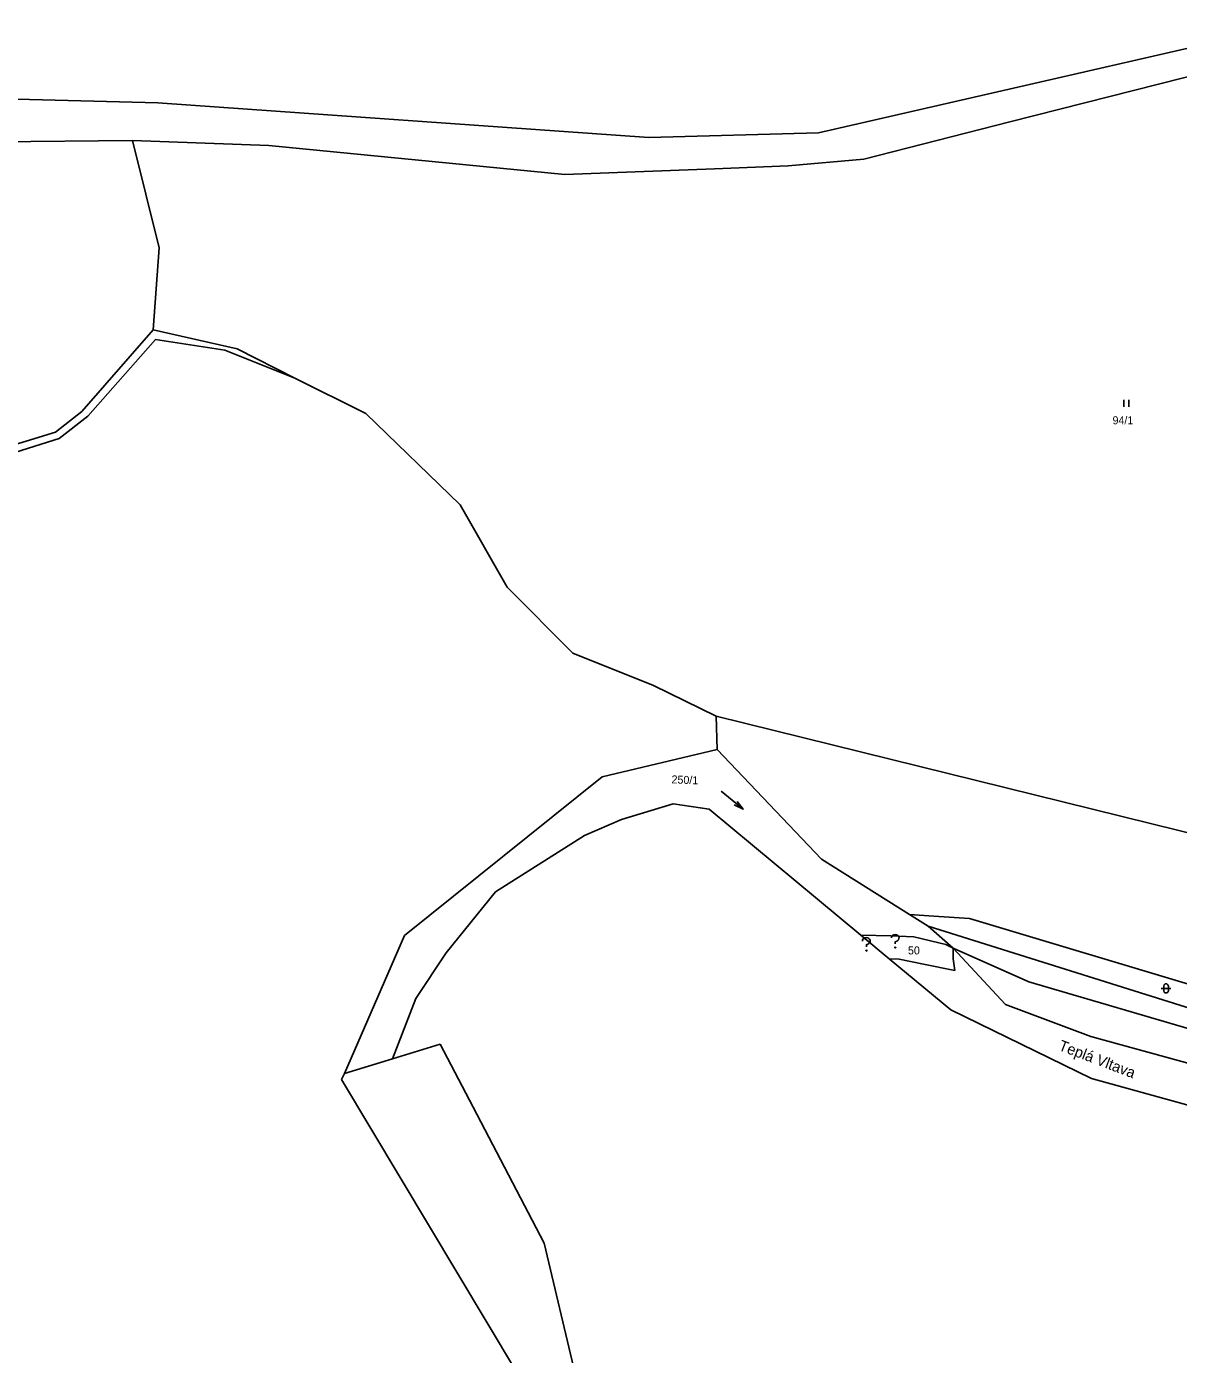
# Model space of a CAD drawing. Extents: x -811039 to -805820, y -1161436 to -1155864.
# Drawn here: x -809634.1 to -809389.3, y -1160727.4 to -1160445.2 of the extents above; entities that cross this region are included whole.
import ezdxf

# ---------------------------------------------------------------- set-up
doc = ezdxf.new("R2010")
doc.units = 0
for name, color, linetype in [('Default', 7, 'Continuous'), ('Hranice kat_území', 7, 'Continuous'), ('Hranice parcel', 7, 'Continuous'), ('Parcelní čísla', 7, 'Continuous'), ('Pop  PČ popisy', 7, 'Continuous'), ('Značky budov', 7, 'Continuous'), ('Značky kultur', 7, 'Continuous')]:
    doc.layers.add(name, color=color, linetype=linetype)

# ---------------------------------------------------------------- blocks, each defined once
blk = doc.blocks.new('306')
at = {"layer": 'Default'}
for p, q in [((-0.5, 1.5), (-0.5, 0)), ((0.5, 0), (0.5, 1.5))]:
    blk.add_line(p, q, dxfattribs=at)
blk = doc.blocks.new('316')
at = {"layer": 'Default'}
for points in [[(-1, 1), (0.27, 1), (1, 1)], [(-0.5, 1.5), (-0.4, 1.79), (-0.15, 1.97), (0.16, 1.97), (0.41, 1.79), (0.51, 1.5), (0.51, 0.5), (0.41, 0.21), (0.16, 0.03), (-0.15, 0.03), (-0.4, 0.21), (-0.5, 0.5), (-0.5, 1.5)]]:
    blk.add_lwpolyline(points, dxfattribs=at)
blk = doc.blocks.new('802')
at = {"layer": 'Default'}
blk.add_line((-3, 0), (3, 0), dxfattribs=at)
blk.add_lwpolyline([(1, 0.5), (3, 0), (1, -0.5)], dxfattribs=at)
blk = doc.blocks.new('$399')
at = {"layer": 'Default'}
for points in [[(-0.83, 2.06), (-0.83, 2.21), (-0.72, 2.42), (-0.56, 2.6), (-0.3, 2.74), (0, 2.79), (0.28, 2.74), (0.53, 2.61), (0.66, 2.47), (0.8, 2.21), (0.79, 1.92), (0.66, 1.68), (0.53, 1.52), (0.3, 1.38), (-0.01, 1.27), (-0.01, 0.84)], [(0, 0.15), (-0.13, 0.02), (0, -0.11), (0.13, 0.02), (0, 0.15)]]:
    blk.add_lwpolyline(points, dxfattribs=at)

msp = doc.modelspace()

# ---------------------------------------------------------------- linework, layer by layer
at = {"layer": 'Hranice kat_území'}
for p, q in [((-809496.7, -1160610.38), (-809507.65, -1160613.68)), ((-809489.01, -1160611.47), (-809496.7, -1160610.38)), ((-809456.76, -1160638.29), (-809489.01, -1160611.47)), ((-809507.65, -1160613.68), (-809515.54, -1160617.09)), ((-809515.54, -1160617.09), (-809534.43, -1160629.07)), ((-809534.43, -1160629.07), (-809544.94, -1160642.01)), ((-809450.76, -1160643.28), (-809456.76, -1160638.29)), ((-809544.94, -1160642.01), (-809551.36, -1160651.74)), ((-809437.67, -1160654.17), (-809450.76, -1160643.28)), ((-809551.36, -1160651.74), (-809556.37, -1160664.59)), ((-809407.74, -1160668.76), (-809437.67, -1160654.17)), ((-809556.37, -1160664.59), (-809546.17, -1160661.43)), ((-809546.17, -1160661.43), (-809538.39, -1160676.28)), ((-809356.9, -1160682.85), (-809407.74, -1160668.76)), ((-809538.39, -1160676.28), (-809524.07, -1160703.76)), ((-809524.07, -1160703.76), (-809517.5, -1160731.52))]:
    msp.add_line(p, q, dxfattribs=at)
at = {"layer": 'Hranice parcel'}
for p, q in [((-809465.78, -1160467.81), (-809367.32, -1160445.21)), ((-809365.99, -1160450.5), (-809425.11, -1160465.49)), ((-809636.19, -1160460.63), (-809606.19, -1160461.43)), ((-809606.19, -1160461.43), (-809501.82, -1160468.79)), ((-809425.11, -1160465.49), (-809456.14, -1160473.41)), ((-809611.58, -1160469.43), (-809656.31, -1160469.91)), ((-809611.58, -1160469.43), (-809605.94, -1160492.23)), ((-809582.61, -1160470.48), (-809611.58, -1160469.43)), ((-809501.82, -1160468.79), (-809465.78, -1160467.81)), ((-809519.72, -1160476.62), (-809582.61, -1160470.48)), ((-809487.89, -1160475.44), (-809519.72, -1160476.62)), ((-809472.23, -1160474.79), (-809487.89, -1160475.44)), ((-809456.14, -1160473.41), (-809472.23, -1160474.79)), ((-809605.94, -1160492.23), (-809607.23, -1160509.66)), ((-809607.23, -1160509.66), (-809622.38, -1160526.98)), ((-809589.37, -1160513.69), (-809607.23, -1160509.66)), ((-809621.1, -1160528.01), (-809606.69, -1160511.68)), ((-809606.69, -1160511.68), (-809591.96, -1160513.96)), ((-809591.96, -1160513.96), (-809577.11, -1160519.95)), ((-809577.11, -1160519.95), (-809589.37, -1160513.69)), ((-809577.11, -1160519.95), (-809561.97, -1160527.45)), ((-809622.38, -1160526.98), (-809627.95, -1160531.37)), ((-809627.19, -1160532.74), (-809621.1, -1160528.01)), ((-809541.98, -1160546.82), (-809561.97, -1160527.45)), ((-809627.95, -1160531.37), (-809665.68, -1160543.05)), ((-809664.6, -1160544.58), (-809627.19, -1160532.74)), ((-809541.98, -1160546.82), (-809531.94, -1160564.34)), ((-809531.94, -1160564.34), (-809517.98, -1160578.36)), ((-809517.98, -1160578.36), (-809500.89, -1160585.21)), ((-809500.89, -1160585.21), (-809487.54, -1160591.74)), ((-809487.54, -1160591.74), (-809350.28, -1160625.64)), ((-809487.54, -1160591.74), (-809487.3, -1160598.81)), ((-809487.3, -1160598.81), (-809511.74, -1160604.6)), ((-809487.3, -1160598.81), (-809465.16, -1160622.11)), ((-809511.74, -1160604.6), (-809553.81, -1160638.38)), ((-809446.42, -1160633.89), (-809465.16, -1160622.11)), ((-809441.25, -1160634.23), (-809446.42, -1160633.89)), ((-809442.45, -1160636.38), (-809446.42, -1160633.89)), ((-809370.26, -1160659.02), (-809442.45, -1160636.38)), ((-809442.45, -1160636.38), (-809437.13, -1160641.06)), ((-809433.66, -1160634.73), (-809441.25, -1160634.23)), ((-809358.61, -1160657.26), (-809433.66, -1160634.73)), ((-809553.81, -1160638.38), (-809566.52, -1160667.67)), ((-809456.76, -1160638.29), (-809450.36, -1160638.45)), ((-809450.36, -1160638.45), (-809445.53, -1160638.61)), ((-809445.53, -1160638.61), (-809438.73, -1160640.25)), ((-809438.73, -1160640.25), (-809437.13, -1160641.06)), ((-809437.13, -1160641.06), (-809437.16, -1160643.33)), ((-809421.07, -1160648.18), (-809437.13, -1160641.06)), ((-809426.03, -1160653.03), (-809437.13, -1160641.06)), ((-809448.66, -1160643.35), (-809450.76, -1160643.28)), ((-809443.5, -1160644.42), (-809448.66, -1160643.35)), ((-809436.79, -1160645.82), (-809443.5, -1160644.42)), ((-809437.16, -1160643.33), (-809436.79, -1160645.82)), ((-809421.07, -1160648.18), (-809367.17, -1160663.97)), ((-809407.93, -1160659.83), (-809426.03, -1160653.03)), ((-809355.04, -1160674.38), (-809407.93, -1160659.83)), ((-809566.52, -1160667.67), (-809556.37, -1160664.59)), ((-809566.52, -1160667.67), (-809567.18, -1160668.94)), ((-809567.18, -1160668.94), (-809529.95, -1160731.07))]:
    msp.add_line(p, q, dxfattribs=at)

# ---------------------------------------------------------------- block references
at = {"layer": 'Značky budov'}
for p in [(-809455.61, -1160641.58), (-809449.47, -1160640.93)]:
    msp.add_blockref('$399', p, dxfattribs=at)
at = {"layer": 'Značky kultur'}
for name, p in [('306', (-809400.36, -1160526.04)), ('316', (-809391.92, -1160650.59))]:
    msp.add_blockref(name, p, dxfattribs=at)
at = {"layer": 'Značky kultur', "rotation": -39.71659300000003}
msp.add_blockref('802', (-809484.14, -1160609.59), dxfattribs=at)

# ---------------------------------------------------------------- texts
at = {"layer": 'Parcelní čísla'}
for s, p in [('94/1', (-809403.29, -1160529.72)), ('50', (-809446.77, -1160642.37))]:
    msp.add_text(s, height=1.7, dxfattribs=at).set_placement(p)
msp.add_text('250/1', height=1.7, rotation=357.755, dxfattribs=at).set_placement((-809497.06, -1160606.01))
at = {"layer": 'Pop  PČ popisy'}
msp.add_text('Teplá Vltava', height=2.3, rotation=339.076, dxfattribs=at).set_placement((-809414.93, -1160662.63))

doc.saveas('drawing.dxf')
